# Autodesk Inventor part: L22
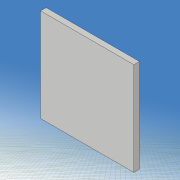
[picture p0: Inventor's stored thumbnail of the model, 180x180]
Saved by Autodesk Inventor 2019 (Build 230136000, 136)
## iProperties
Created: 2021-05
Part Number: L22
Material: 一般
Document SubType Name: Modeling
Designer: kikut
Density: 1 g/cm^3
Appearance: 既定
Mass: 0.00934248 g
Surface Area: 0.426451 cm^2
Volume: 0.00934248 cm^3
Author: kikut
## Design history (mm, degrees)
sketch "スケッチ1"
  geometry: L1 (80, 60)-(-80, 60); L2 (-80, 60)-(-80, -60); L3 (-80, -60)-(80, -60); L4 (80, -60)-(80, 60); L5 (80, 60)-(-80, -60); L6 (-80, 60)-(80, -60); 1 further point
  constraints: 12 end point, 2 midpoint, 2 parallel, 1 horizontal, 1 perpendicular
  dimensions: "d0" = 160 distance of L2.end L3.end; "d1" = 120 distance of L1.end L2.end
extrude "押し出し1" new body sketch "スケッチ1" stored distance "d2" = 0.6; taper "d3" = 0 deg
sketch "スケッチ2"
  geometry: L1 (-140, 0)-(140, 0) reference; L2 (0, -54)-(20, -30); L3 (0, 54)-(20, 30); L4 (0, -3)-(6.514, -3); L5 (6.514, -3)-(16, -6); L6 (16, -6)-(24, -3); L7 (24, -3)-(33.716, -3); L8 (0, 3)-(6.514, 3); L9 (6.514, 3)-(16, 6); L10 (16, 6)-(24, 3); L11 (24, 3)-(33.716, 3); L12 (0, -98)-(0, 98) reference; L13 (-100, -70)-(100, -70); L14 (100, -70)-(100, 70); L15 (100, 70)-(-100, 70); L16 (-100, 70)-(-100, -70); L17 (-100, -70)-(100, 70); L18 (100, -70)-(-100, 70); A1 r 60 centre (54.312, 28.5) between (0, 54) and (0, 3); A2 r 60 centre (54.312, -28.5) between (0, -3) and (0, -54); A3 r 18.111 centre (18, -12) between (20, -30) and (33.716, -3); A4 r 18.111 centre (18, 12) between (33.716, 3) and (20, 30); 1 further point
  constraints: 32 end point, 8 point on circle, 8 symmetric about line, 4 centre point, 3 horizontal, 2 collinear, 2 midpoint, 2 parallel, 1 perpendicular
  dimensions: "d5" = 60 radius of A1; "d6" = 6 distance of L8.start L4.start; "d7" = 108 distance of L3.start L2.start; "d8" = 0 horizontal distance of L3.start L8.start; "d9" = 60 distance of L3.end L2.end; "d10" = 0 horizontal distance of point (0, 0) L3.start; "d11" = 20 horizontal distance of L3.start L3.end; "d12" = 24 distance of A4.centre A3.centre; "d13" = 6 distance of L11.end L7.end; "d14" = 12 distance of L9.end L5.end; "d15" = 16 distance from line of L12 L5.end; "d16" = 24 distance from line of L6.end L12; "d17" = 200 distance of L14.end L15.end; "d18" = 140 distance of L15.end L13.start; "d30" = 18 distance from line of L12 A4.centre
extrude "押し出し2" cut sketch "スケッチ2" stored distance "d19" = 10; taper "d20" = 0 deg
sketch "スケッチ3"
  geometry: L1 (49.705, -17.97)-(33.948, -15.191); L2 (33.948, -15.191)-(34.295, -13.222); L3 (34.295, -13.222)-(50.052, -16); L4 (50.052, -16)-(49.705, -17.97); L5 (49.705, -17.97)-(34.295, -13.222); L6 (33.948, -15.191)-(50.052, -16); L7 (50.052, 16)-(34.295, 13.222); L8 (34.295, 13.222)-(33.948, 15.191); L9 (33.948, 15.191)-(49.705, 17.97); L10 (49.705, 17.97)-(50.052, 16); L11 (50.052, 16)-(33.948, 15.191); L12 (34.295, 13.222)-(49.705, 17.97); L13 (-112, 0)-(112, 0) reference; L14 (0, -84)-(0, 84) reference; 3 further points
  constraints: 24 end point, 4 midpoint, 4 parallel, 2 perpendicular, 2 symmetric about line
  dimensions: "d21" = 2 distance of L3.end L1.start; "d22" = 2 distance of L9.end L7.start; "d23" = 16 distance of L8.end L9.end; "d24" = 42 distance from line of L14 point (42, 15.596); "d26" = 10 deg angle of L7 L13; "d62" = 16 distance from line of L3.end L13
extrude "押し出し3" join sketch "スケッチ3" distance "d27" = 0.6; taper "d28" = 0 deg
fillet "フィレット1" dims "d31" = 2
fillet "フィレット2" dims "d32" = 1
sketch "スケッチ7"
  geometry: L1 (-20, 60)-(80, 60); L2 (80, 60)-(80, -60); L3 (80, -60)-(-20, -60); L4 (-20, -60)-(-20, 60); L5 (0, -82.207)-(0, 85.793) reference; L6 (-40, 0)-(100, 0) reference; L7 (10, -20)-(20, -20); L8 (20, -20)-(20, -30); L9 (20, -30)-(10, -30); L10 (10, -30)-(10, -20); 1 further point
  constraints: 16 end point, 4 parallel, 2 horizontal, 2 perpendicular, 1 other
  dimensions: "d80" = 120 distance of L3.end L1.start; "d81" = 20 distance between parallel lines of L5 L4; "d82" = 100 distance of L1.start L1.end; "d84" = 10 distance of L8.end L9.end; "d85" = 10 distance of L7.end L8.end; "d86" = 30 distance between parallel lines of L4 L10; "d91" = 30 distance between parallel lines of L3 L9
extrude "押し出し5" cut sketch "スケッチ7" stored distance "d87" = 10; taper "d88" = 0 deg
node "ソリッド1"
